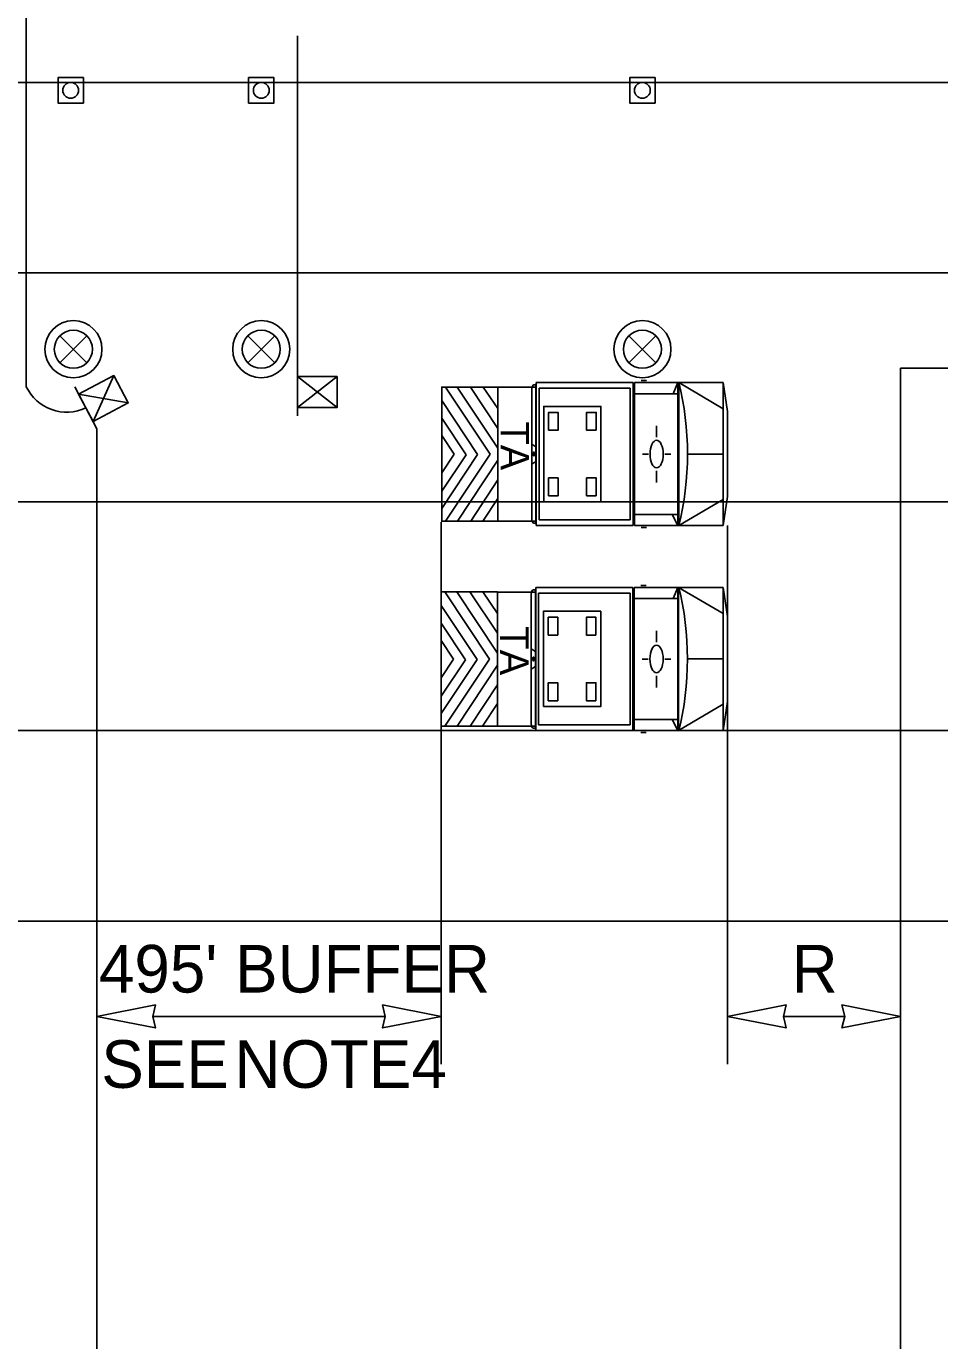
# Model space of a CAD drawing. Extents: x 99999 to 100116, y 99995 to 100013.
# Drawn here: x 100072.995 to 100074.529, y 100006.086 to 100008.293 of the extents above; entities that cross this region are included whole.
import ezdxf

# ---------------------------------------------------------------- set-up
doc = ezdxf.new("R2010")
doc.units = 0
for name, color, linetype in [('RD_MK_LineEdgeYellow', 7, 'Continuous'), ('RD_MK_LineLane', 7, 'Continuous'), ('TR_WZ_PortableSignMount5ftMinBlk-Org', 7, 'Continuous'), ('TR_WZ_PortableSignMount5ftMinBlk-Wht', 7, 'Continuous'), ('TR_WZ_TrafficCone', 7, 'Continuous'), ('TR_WZ_TrafficSafetyDrum', 7, 'Continuous'), ('TR_WZ_TransportableAttenuator', 7, 'Continuous'), ('TR_WZ_WorkZoneDetails', 7, 'Continuous'), ('TR_WZ_WorkZoneTextCurrent', 7, 'Continuous')]:
    doc.layers.add(name, color=color, linetype=linetype)

msp = doc.modelspace()

# ---------------------------------------------------------------- linework, layer by layer
at = {"layer": 'RD_MK_LineEdgeYellow'}
for p, q in [((100068.195, 100007.8789), (100075.43, 100007.8789)), ((100072.7368, 100007.1109), (100075.43, 100007.1109))]:
    msp.add_line(p, q, dxfattribs=at)
at = {"layer": 'RD_MK_LineLane'}
msp.add_lwpolyline([(100075.43, 100007.4949), (100068.195, 100007.4949)], dxfattribs=at)
at = {"layer": 'TR_WZ_PortableSignMount5ftMinBlk-Org'}
for p, q in [((100073.1417, 100007.7067), (100073.107, 100007.6295)), ((100073.1135, 100007.6171), (100073.0761, 100007.6879)), ((100073.166, 100007.6607), (100073.0827, 100007.6755)), ((100073.1243, 100007.6681), (100073.1243, 100007.6681)), ((100073.1244, 100007.6682), (100073.1244, 100007.6682))]:
    msp.add_line(p, q, dxfattribs=at)
for points in [[(100073.1417, 100007.7067), (100073.166, 100007.6607), (100073.107, 100007.6295), (100073.0827, 100007.6755)], [(100073.107, 100007.6295), (100073.166, 100007.6607), (100073.1417, 100007.7067), (100073.0827, 100007.6755)]]:
    msp.add_lwpolyline(points, close=True, dxfattribs=at)
at = {"layer": 'TR_WZ_PortableSignMount5ftMinBlk-Wht'}
for p, q in [((100073.45, 100007.6389), (100073.45, 100007.7189)), ((100073.5167, 100007.7049), (100073.45, 100007.6529)), ((100073.5167, 100007.6529), (100073.45, 100007.7049)), ((100073.4834, 100007.6789), (100073.4834, 100007.6789)), ((100073.4835, 100007.679), (100073.4835, 100007.679))]:
    msp.add_line(p, q, dxfattribs=at)
msp.add_lwpolyline([(100073.5167, 100007.7049), (100073.5167, 100007.6529), (100073.45, 100007.6529), (100073.45, 100007.7049)], close=True, dxfattribs=at)
at = {"layer": 'TR_WZ_TrafficCone'}
for points in [[(100073.0481, 100008.2069), (100073.0907, 100008.2069), (100073.0907, 100008.1642), (100073.0481, 100008.1642), (100073.0481, 100008.2069)], [(100073.0481, 100008.1642), (100073.0907, 100008.1642), (100073.0907, 100008.2069), (100073.0481, 100008.2069), (100073.0481, 100008.1642)], [(100073.3681, 100008.2069), (100073.4107, 100008.2069), (100073.4107, 100008.1642), (100073.3681, 100008.1642), (100073.3681, 100008.2069)], [(100073.3681, 100008.1642), (100073.4107, 100008.1642), (100073.4107, 100008.2069), (100073.3681, 100008.2069), (100073.3681, 100008.1642)], [(100074.0081, 100008.2069), (100074.0507, 100008.2069), (100074.0507, 100008.1642), (100074.0081, 100008.1642), (100074.0081, 100008.2069)], [(100074.0081, 100008.1642), (100074.0507, 100008.1642), (100074.0507, 100008.2069), (100074.0081, 100008.2069), (100074.0081, 100008.1642)]]:
    msp.add_lwpolyline(points, dxfattribs=at)
for centre in [(100073.0694, 100008.1856), (100073.3894, 100008.1856), (100074.0294, 100008.1856)]:
    msp.add_circle(centre, 0.0133, dxfattribs=at)
at = {"layer": 'TR_WZ_TrafficSafetyDrum'}
for p, q in [((100073.0513, 100007.7735), (100073.0966, 100007.7283)), ((100073.0966, 100007.7735), (100073.0513, 100007.7283)), ((100073.3668, 100007.7735), (100073.412, 100007.7283)), ((100073.412, 100007.7735), (100073.3668, 100007.7283)), ((100074.0068, 100007.7735), (100074.052, 100007.7283)), ((100074.052, 100007.7735), (100074.0068, 100007.7283))]:
    msp.add_line(p, q, dxfattribs=at)
for centre, radius in [((100073.0739, 100007.7509), 0.048), ((100073.0739, 100007.7509), 0.048), ((100073.3894, 100007.7509), 0.048), ((100073.3894, 100007.7509), 0.048), ((100074.0294, 100007.7509), 0.048), ((100074.0294, 100007.7509), 0.048), ((100073.0739, 100007.7509), 0.032), ((100073.3894, 100007.7509), 0.032), ((100074.0294, 100007.7509), 0.032)]:
    msp.add_circle(centre, radius, dxfattribs=at)
at = {"layer": 'TR_WZ_TransportableAttenuator'}
for p, q in [((100073.7186, 100007.6875), (100073.6986, 100007.6875)), ((100073.6986, 100007.6875), (100073.7735, 100007.5747)), ((100073.7735, 100007.5747), (100073.6986, 100007.6875)), ((100073.6986, 100007.6875), (100073.7186, 100007.6875)), ((100073.7868, 100007.5848), (100073.7186, 100007.6875)), ((100073.7186, 100007.6875), (100073.7868, 100007.5848)), ((100073.7622, 100007.6875), (100073.7406, 100007.6875)), ((100073.7406, 100007.6875), (100073.7868, 100007.618)), ((100073.7868, 100007.618), (100073.7406, 100007.6875)), ((100073.7406, 100007.6875), (100073.7622, 100007.6875)), ((100073.7868, 100007.6512), (100073.7622, 100007.6875)), ((100073.7622, 100007.6875), (100073.7868, 100007.6512)), ((100073.8512, 100007.6873), (100073.7868, 100007.6873)), ((100073.7868, 100007.6873), (100073.7868, 100007.462)), ((100073.8436, 100007.4662), (100073.8436, 100007.6837)), ((100073.8471, 100007.691), (100073.8506, 100007.691)), ((100073.8506, 100007.4589), (100073.8506, 100007.691)), ((100073.8512, 100007.6949), (100074.0137, 100007.6949)), ((100073.8512, 100007.4549), (100073.8512, 100007.6949)), ((100073.8512, 100007.4624), (100073.8512, 100007.6873)), ((100073.8558, 100007.4645), (100073.8558, 100007.6853)), ((100073.8558, 100007.6853), (100074.0091, 100007.6853)), ((100074.0091, 100007.4645), (100074.0091, 100007.6853)), ((100074.0137, 100007.4549), (100074.0137, 100007.6949)), ((100074.0159, 100007.4549), (100074.0159, 100007.6949)), ((100074.1651, 100007.6949), (100074.0159, 100007.6949)), ((100074.0362, 100007.6983), (100074.0273, 100007.6983)), ((100074.0813, 100007.6763), (100074.0891, 100007.6949)), ((100074.0891, 100007.4549), (100074.0891, 100007.6949)), ((100074.0905, 100007.4549), (100074.0905, 100007.6949)), ((100074.1651, 100007.651), (100074.0905, 100007.6949)), ((100074.1651, 100007.4549), (100074.1651, 100007.6949)), ((100074.1651, 100007.6949), (100074.1724, 100007.6465)), ((100073.7525, 100007.574), (100073.6924, 100007.6646)), ((100073.6924, 100007.6646), (100073.6924, 100007.6351)), ((100073.6924, 100007.6351), (100073.6924, 100007.6646)), ((100073.6924, 100007.6646), (100073.7525, 100007.574)), ((100074.0891, 100007.6763), (100074.0159, 100007.6763)), ((100073.7868, 100007.618), (100073.7868, 100007.6512)), ((100073.7868, 100007.6512), (100073.7868, 100007.618)), ((100074.1724, 100007.5034), (100074.1724, 100007.6465)), ((100073.6924, 100007.6351), (100073.7332, 100007.5737)), ((100073.7332, 100007.5737), (100073.6924, 100007.6351)), ((100074.0533, 100007.6225), (100074.0533, 100007.6031)), ((100073.7133, 100007.5746), (100073.6924, 100007.606)), ((100073.6924, 100007.606), (100073.6924, 100007.5435)), ((100073.6924, 100007.606), (100073.7133, 100007.5746)), ((100073.6924, 100007.5435), (100073.6924, 100007.606)), ((100073.6924, 100007.5435), (100073.7133, 100007.5746)), ((100073.7133, 100007.5746), (100073.6924, 100007.5435)), ((100073.6924, 100007.4835), (100073.7525, 100007.574)), ((100073.7525, 100007.574), (100073.6924, 100007.4835)), ((100073.7332, 100007.5737), (100073.6924, 100007.5126)), ((100073.6924, 100007.5126), (100073.7332, 100007.5737)), ((100073.7735, 100007.5747), (100073.6986, 100007.462)), ((100073.6986, 100007.462), (100073.7735, 100007.5747)), ((100073.7868, 100007.5648), (100073.7868, 100007.5848)), ((100073.7868, 100007.5848), (100073.7868, 100007.5648)), ((100073.8436, 100007.5918), (100073.8506, 100007.5873)), ((100073.8455, 100007.5749), (100073.8487, 100007.5749)), ((100073.8471, 100007.5716), (100073.8471, 100007.5783)), ((100074.0295, 100007.5748), (100074.0394, 100007.5748)), ((100074.0422, 100007.5753), (100074.0422, 100007.5753)), ((100074.0771, 100007.5748), (100074.0672, 100007.5748)), ((100074.1651, 100007.5749), (100074.1051, 100007.5749)), ((100073.719, 100007.462), (100073.7868, 100007.5648)), ((100073.7868, 100007.5648), (100073.719, 100007.462)), ((100073.8436, 100007.558), (100073.8506, 100007.5625)), ((100073.7868, 100007.5315), (100073.7412, 100007.462)), ((100073.7412, 100007.462), (100073.7868, 100007.5315)), ((100073.7868, 100007.5002), (100073.7868, 100007.5315)), ((100073.7868, 100007.5315), (100073.7868, 100007.5002)), ((100074.0533, 100007.5274), (100074.0533, 100007.5468)), ((100073.6924, 100007.5126), (100073.6924, 100007.4835)), ((100073.6924, 100007.4835), (100073.6924, 100007.5126)), ((100073.7615, 100007.462), (100073.7868, 100007.5002)), ((100073.7868, 100007.5002), (100073.7615, 100007.462)), ((100074.1651, 100007.4989), (100074.0905, 100007.4549)), ((100074.1651, 100007.4549), (100074.1724, 100007.5034)), ((100073.8558, 100007.4645), (100074.0091, 100007.4645)), ((100074.0891, 100007.4735), (100074.0159, 100007.4735)), ((100074.0891, 100007.4549), (100074.0796, 100007.4735)), ((100073.6986, 100007.462), (100073.719, 100007.462)), ((100073.719, 100007.462), (100073.6986, 100007.462)), ((100073.7412, 100007.462), (100073.7615, 100007.462)), ((100073.7615, 100007.462), (100073.7412, 100007.462)), ((100073.8512, 100007.462), (100073.7868, 100007.462)), ((100073.8471, 100007.4589), (100073.8506, 100007.4589)), ((100073.8512, 100007.4549), (100074.0137, 100007.4549)), ((100074.1651, 100007.4549), (100074.0159, 100007.4549)), ((100074.0362, 100007.4515), (100074.0273, 100007.4515)), ((100074.0359, 100007.3543), (100074.027, 100007.3543)), ((100073.7177, 100007.3435), (100073.6976, 100007.3435)), ((100073.6976, 100007.3435), (100073.7727, 100007.2307)), ((100073.7727, 100007.2307), (100073.6976, 100007.3435)), ((100073.6976, 100007.3435), (100073.7177, 100007.3435)), ((100073.786, 100007.2408), (100073.7177, 100007.3435)), ((100073.7177, 100007.3435), (100073.786, 100007.2408)), ((100073.7614, 100007.3435), (100073.7398, 100007.3435)), ((100073.7398, 100007.3435), (100073.786, 100007.274)), ((100073.786, 100007.274), (100073.7398, 100007.3435)), ((100073.7398, 100007.3435), (100073.7614, 100007.3435)), ((100073.786, 100007.3071), (100073.7614, 100007.3435)), ((100073.7614, 100007.3435), (100073.786, 100007.3071)), ((100073.8505, 100007.3433), (100073.786, 100007.3433)), ((100073.786, 100007.3433), (100073.786, 100007.118)), ((100073.8429, 100007.1221), (100073.8429, 100007.3396)), ((100073.8464, 100007.347), (100073.85, 100007.347)), ((100073.85, 100007.1148), (100073.85, 100007.347)), ((100073.8505, 100007.3509), (100074.0134, 100007.3509)), ((100073.8505, 100007.1109), (100073.8505, 100007.3509)), ((100073.8505, 100007.1184), (100073.8505, 100007.3433)), ((100073.8551, 100007.1205), (100073.8551, 100007.3413)), ((100073.8551, 100007.3413), (100074.0088, 100007.3413)), ((100074.0088, 100007.1205), (100074.0088, 100007.3413)), ((100074.0134, 100007.1109), (100074.0134, 100007.3509)), ((100074.0156, 100007.1109), (100074.0156, 100007.3509)), ((100074.1651, 100007.3509), (100074.0156, 100007.3509)), ((100074.089, 100007.3323), (100074.0156, 100007.3323)), ((100074.0811, 100007.3323), (100074.089, 100007.3509)), ((100074.089, 100007.1109), (100074.089, 100007.3509)), ((100074.0903, 100007.1109), (100074.0903, 100007.3509)), ((100074.1651, 100007.307), (100074.0903, 100007.3509)), ((100074.1651, 100007.1109), (100074.1651, 100007.3509)), ((100074.1651, 100007.3509), (100074.1724, 100007.3024)), ((100073.7517, 100007.23), (100073.6914, 100007.3205)), ((100073.6914, 100007.3205), (100073.6914, 100007.2911)), ((100073.6914, 100007.2911), (100073.6914, 100007.3205)), ((100073.6914, 100007.3205), (100073.7517, 100007.23)), ((100073.6914, 100007.2911), (100073.7323, 100007.2297)), ((100073.7323, 100007.2297), (100073.6914, 100007.2911)), ((100073.786, 100007.274), (100073.786, 100007.3071)), ((100073.786, 100007.3071), (100073.786, 100007.274)), ((100074.1724, 100007.1593), (100074.1724, 100007.3024)), ((100074.0531, 100007.2784), (100074.0531, 100007.2591)), ((100073.7124, 100007.2305), (100073.6914, 100007.2619)), ((100073.6914, 100007.2619), (100073.6914, 100007.1995)), ((100073.6914, 100007.2619), (100073.7124, 100007.2305)), ((100073.6914, 100007.1995), (100073.6914, 100007.2619)), ((100073.8429, 100007.2478), (100073.85, 100007.2433)), ((100073.6914, 100007.1995), (100073.7124, 100007.2305)), ((100073.7124, 100007.2305), (100073.6914, 100007.1995)), ((100073.6914, 100007.1394), (100073.7517, 100007.23)), ((100073.7517, 100007.23), (100073.6914, 100007.1394)), ((100073.7323, 100007.2297), (100073.6914, 100007.1686)), ((100073.6914, 100007.1686), (100073.7323, 100007.2297)), ((100073.7727, 100007.2307), (100073.6977, 100007.118)), ((100073.6977, 100007.118), (100073.7727, 100007.2307)), ((100073.7181, 100007.118), (100073.786, 100007.2207)), ((100073.786, 100007.2207), (100073.7181, 100007.118)), ((100073.786, 100007.2207), (100073.786, 100007.2408)), ((100073.786, 100007.2408), (100073.786, 100007.2207)), ((100073.8448, 100007.2309), (100073.8481, 100007.2309)), ((100073.8464, 100007.2275), (100073.8464, 100007.2343)), ((100074.0292, 100007.2307), (100074.0392, 100007.2308)), ((100074.0419, 100007.2313), (100074.0419, 100007.2313)), ((100074.0769, 100007.2307), (100074.067, 100007.2308)), ((100074.1651, 100007.2309), (100074.105, 100007.2309)), ((100073.8429, 100007.214), (100073.85, 100007.2185)), ((100074.0531, 100007.1833), (100074.0531, 100007.2027)), ((100073.786, 100007.1875), (100073.7403, 100007.118)), ((100073.7403, 100007.118), (100073.786, 100007.1875)), ((100073.786, 100007.1562), (100073.786, 100007.1875)), ((100073.786, 100007.1875), (100073.786, 100007.1562)), ((100073.6914, 100007.1686), (100073.6914, 100007.1394)), ((100073.6914, 100007.1394), (100073.6914, 100007.1686)), ((100073.7607, 100007.118), (100073.786, 100007.1562)), ((100073.786, 100007.1562), (100073.7607, 100007.118)), ((100074.1651, 100007.1549), (100074.0903, 100007.1109)), ((100074.1651, 100007.1109), (100074.1724, 100007.1593)), ((100073.6977, 100007.118), (100073.7181, 100007.118)), ((100073.7181, 100007.118), (100073.6977, 100007.118)), ((100073.7403, 100007.118), (100073.7607, 100007.118)), ((100073.7607, 100007.118), (100073.7403, 100007.118)), ((100073.8505, 100007.118), (100073.786, 100007.118)), ((100073.8464, 100007.1148), (100073.85, 100007.1148)), ((100073.8505, 100007.1109), (100074.0134, 100007.1109)), ((100073.8551, 100007.1205), (100074.0088, 100007.1205)), ((100074.089, 100007.1295), (100074.0156, 100007.1295)), ((100074.1651, 100007.1109), (100074.0156, 100007.1109)), ((100074.089, 100007.1109), (100074.0795, 100007.1295)), ((100074.0359, 100007.1075), (100074.027, 100007.1075))]:
    msp.add_line(p, q, dxfattribs=at)
for points in [[(100073.7868, 100007.6875), (100073.6924, 100007.6875), (100073.6924, 100007.462), (100073.7868, 100007.462)], [(100073.8638, 100007.4949), (100073.9598, 100007.4949), (100073.9598, 100007.6549), (100073.8638, 100007.6549)], [(100073.8718, 100007.6149), (100073.8878, 100007.6149), (100073.8878, 100007.6449), (100073.8718, 100007.6449)], [(100073.9518, 100007.6149), (100073.9358, 100007.6149), (100073.9358, 100007.6449), (100073.9518, 100007.6449)], [(100073.8718, 100007.5049), (100073.8878, 100007.5049), (100073.8878, 100007.5349), (100073.8718, 100007.5349)], [(100073.9518, 100007.5049), (100073.9358, 100007.5049), (100073.9358, 100007.5349), (100073.9518, 100007.5349)], [(100073.786, 100007.3435), (100073.6914, 100007.3435), (100073.6914, 100007.118), (100073.786, 100007.118)], [(100073.8632, 100007.1509), (100073.9594, 100007.1509), (100073.9594, 100007.3109), (100073.8632, 100007.3109)], [(100073.8712, 100007.2709), (100073.8872, 100007.2709), (100073.8872, 100007.3009), (100073.8712, 100007.3009)], [(100073.9513, 100007.2709), (100073.9353, 100007.2709), (100073.9353, 100007.3009), (100073.9513, 100007.3009)], [(100073.8712, 100007.1609), (100073.8872, 100007.1609), (100073.8872, 100007.1909), (100073.8712, 100007.1909)], [(100073.9513, 100007.1609), (100073.9353, 100007.1609), (100073.9353, 100007.1909), (100073.9513, 100007.1909)]]:
    msp.add_lwpolyline(points, close=True, dxfattribs=at)
for points in [[(100073.7868, 100007.462), (100073.6924, 100007.462), (100073.6924, 100007.6875), (100073.7868, 100007.6873)], [(100073.786, 100007.118), (100073.6914, 100007.118), (100073.6914, 100007.3435), (100073.786, 100007.3433)]]:
    msp.add_lwpolyline(points, dxfattribs=at)
for centre, major_axis, ratio, start_param, end_param in [((100073.8471, 100007.6837), (0, 0.00732), 0.481608, 0, 1.570796), ((100073.9838, 100007.5749), (0, 0.2519), 0.481608, 4.215667, 5.208926), ((100073.8471, 100007.4662), (0, -0.00732), 0.481608, 4.712389, 6.283185), ((100073.8464, 100007.3396), (0, 0.00732), 0.482618, 0, 1.570796), ((100073.9835, 100007.2309), (0, 0.2519), 0.482618, 4.215667, 5.208926), ((100073.8464, 100007.1222), (0, -0.00732), 0.482618, 4.712389, 6.283185)]:
    msp.add_ellipse(centre, major_axis=major_axis, ratio=ratio, start_param=start_param, end_param=end_param, dxfattribs=at)
for centre, major_axis, ratio in [((100074.0533, 100007.5749), (0, -0.0231), 0.481608), ((100073.8471, 100007.5749), (0, -0.00338), 0.481608), ((100074.0531, 100007.2309), (0, -0.0231), 0.482618), ((100073.8464, 100007.2309), (0, -0.00338), 0.482618)]:
    msp.add_ellipse(centre, major_axis=major_axis, ratio=ratio, dxfattribs=at)
at = {"layer": 'TR_WZ_WorkZoneDetails'}
for p, q in [((100072.9948, 100007.6879), (100072.9948, 100008.8048)), ((100073.45, 100007.7111), (100073.45, 100008.2769)), ((100068.195, 100008.1989), (100075.43, 100008.1989)), ((100073.1135, 100007.6171), (100073.1135, 100005.2929)), ((100073.6914, 100007.4607), (100073.6914, 100006.5509)), ((100074.1724, 100007.4548), (100074.1724, 100006.5509)), ((100072.7368, 100006.7909), (100075.43, 100006.7909)), ((100074.4628, 100006.7909), (100074.4628, 100005.1282)), ((100073.5977, 100006.6309), (100073.2072, 100006.6309)), ((100074.3691, 100006.6309), (100074.2662, 100006.6309)), ((100074.3691, 100006.6309), (100074.2662, 100006.6309))]:
    msp.add_line(p, q, dxfattribs=at)
for points in [[(100074.4628, 100007.7189), (100074.4628, 100006.7909), (100075.35, 100006.7909), (100075.35, 100007.7189)], [(100073.1135, 100006.6309), (100073.2118, 100006.6502), (100073.2072, 100006.6309), (100073.2118, 100006.6116)], [(100073.6914, 100006.6309), (100073.5931, 100006.6502), (100073.5977, 100006.6309), (100073.5931, 100006.6116)], [(100074.1724, 100006.6309), (100074.2707, 100006.6502), (100074.2662, 100006.6309), (100074.2707, 100006.6116)], [(100074.4628, 100006.6309), (100074.3645, 100006.6502), (100074.3691, 100006.6309), (100074.3645, 100006.6116)]]:
    msp.add_lwpolyline(points, close=True, dxfattribs=at)
msp.add_arc((100073.0625, 100007.7202), 0.075, 205.5184, 295.5238, dxfattribs=at)

# ---------------------------------------------------------------- texts
at = {"layer": 'TR_WZ_TransportableAttenuator'}
for height, p in [(0.048, (100073.7912, 100007.6298)), (0.0481, (100073.7904, 100007.2858))]:
    msp.add_text('TA', height=height, rotation=270, dxfattribs=at).set_placement(p)
at = {"layer": 'TR_WZ_WorkZoneTextCurrent'}
for s, p in [("495' BUFFER", (100073.1169, 100006.6709)), ('R', (100074.28, 100006.6709)), ('R', (100074.28, 100006.6709)), ('SEE', (100073.1208, 100006.5109)), ('NOTE', (100073.3443, 100006.5109)), ('4', (100073.6415, 100006.5109))]:
    msp.add_text(s, height=0.08, dxfattribs=at).set_placement(p)

doc.saveas('drawing.dxf')
